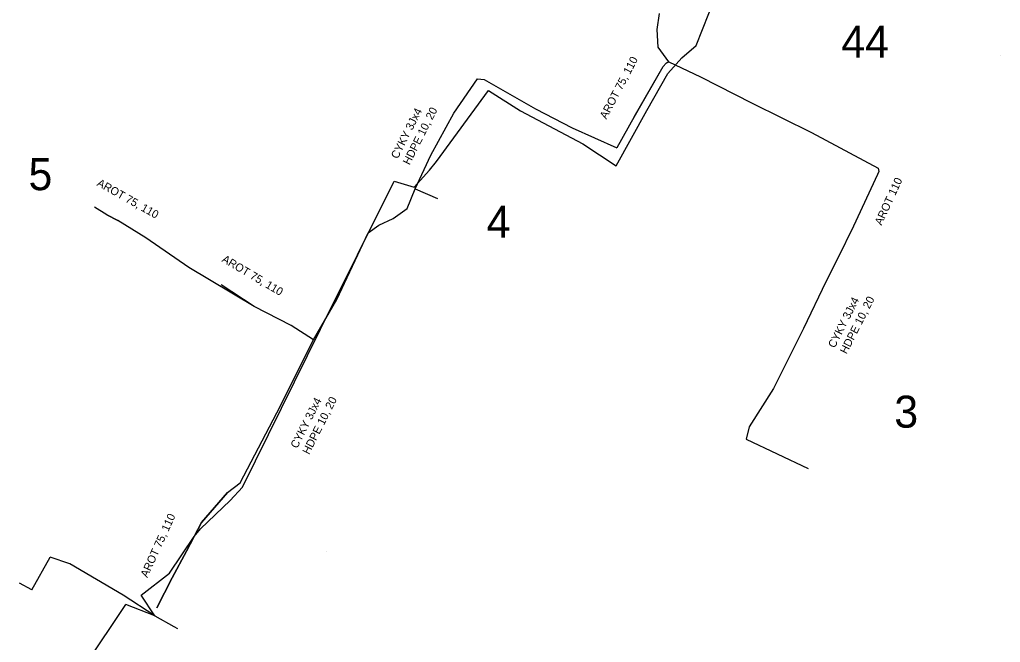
# Model space of a CAD drawing. Extents: x -651943 to -618711, y -1138561 to -1100552.
# Drawn here: x -642518.9 to -642427, y -1114396.7 to -1114338.4 of the extents above; entities that cross this region are included whole.
import ezdxf

# ---------------------------------------------------------------- set-up
doc = ezdxf.new("R2010")
doc.units = 0
for name, color, linetype in [('KT optika', 7, 'Continuous'), ('KT trasa', 7, 'Continuous'), ('KT zařízení', 7, 'Continuous'), ('SATT bloky', 7, 'Continuous'), ('SATT stanice', 7, 'Continuous')]:
    doc.layers.add(name, color=color, linetype=linetype)

# ---------------------------------------------------------------- blocks, each defined once
blk = doc.blocks.new('POINT_DISPLAY')
blk.add_line((0, 0), (0, 0))

msp = doc.modelspace()

# ---------------------------------------------------------------- linework, layer by layer
at = {"layer": 'KT optika'}
for p, q in [((-642459.15, -1114339.29), (-642458.96, -1114337.79)), ((-642459.08, -1114340.92), (-642459.15, -1114339.29)), ((-642458.07, -1114342.31), (-642459.08, -1114340.92)), ((-642461.31, -1114347.46), (-642458.59, -1114342.76)), ((-642458.31, -1114342.44), (-642458.59, -1114342.76)), ((-642458.07, -1114342.31), (-642458.31, -1114342.44)), ((-642458.07, -1114342.31), (-642455.1, -1114343.7)), ((-642455.1, -1114343.7), (-642450.26, -1114346.17)), ((-642478.23, -1114347.12), (-642476.01, -1114343.9)), ((-642476.01, -1114343.9), (-642475.37, -1114343.95)), ((-642475.37, -1114343.95), (-642470.55, -1114346.71)), ((-642450.26, -1114346.17), (-642444.69, -1114348.92)), ((-642480.38, -1114351.06), (-642478.23, -1114347.12)), ((-642470.55, -1114346.71), (-642467.12, -1114348.48)), ((-642461.31, -1114347.46), (-642462.95, -1114350.38)), ((-642467.12, -1114348.48), (-642462.95, -1114350.38)), ((-642444.69, -1114348.92), (-642438.45, -1114352.26)), ((-642481.85, -1114354.22), (-642480.38, -1114351.06)), ((-642438.51, -1114352.85), (-642440.75, -1114357.71)), ((-642438.4, -1114352.57), (-642438.51, -1114352.85)), ((-642438.45, -1114352.26), (-642438.4, -1114352.57)), ((-642482.59, -1114356.04), (-642481.85, -1114354.22)), ((-642481.85, -1114354.22), (-642479.75, -1114355.1)), ((-642510.73, -1114356.65), (-642511.9, -1114355.94)), ((-642510.73, -1114356.65), (-642509.7, -1114357.18)), ((-642483.9, -1114356.99), (-642482.59, -1114356.04)), ((-642507.08, -1114358.81), (-642509.7, -1114357.18)), ((-642486.23, -1114358.32), (-642485.24, -1114357.62)), ((-642485.24, -1114357.62), (-642483.9, -1114356.99)), ((-642489.19, -1114364.58), (-642486.23, -1114358.32)), ((-642440.75, -1114357.71), (-642442.24, -1114360.7)), ((-642503.05, -1114361.57), (-642507.08, -1114358.81)), ((-642442.24, -1114360.7), (-642443.36, -1114362.92)), ((-642496.94, -1114365.23), (-642503.05, -1114361.57)), ((-642443.36, -1114362.92), (-642445.45, -1114367.28)), ((-642491.36, -1114368.35), (-642489.19, -1114364.58)), ((-642493.46, -1114367.02), (-642496.94, -1114365.23)), ((-642491.36, -1114368.35), (-642493.46, -1114367.02)), ((-642445.45, -1114367.28), (-642448.27, -1114372.9)), ((-642494.47, -1114374.51), (-642491.36, -1114368.35)), ((-642448.27, -1114372.9), (-642450.54, -1114376.49)), ((-642498.25, -1114381.76), (-642494.47, -1114374.53)), ((-642494.47, -1114374.53), (-642494.47, -1114374.51)), ((-642450.54, -1114376.49), (-642450.81, -1114377.65)), ((-642450.81, -1114377.65), (-642445.02, -1114380.412)), ((-642499.42, -1114382.67), (-642498.25, -1114381.76)), ((-642499.42, -1114382.67), (-642501.85, -1114385.47)), ((-642501.85, -1114385.47), (-642503.27, -1114388.15)), ((-642503.27, -1114388.15), (-642504.61, -1114390.65)), ((-642504.61, -1114390.65), (-642506.04, -1114393.47))]:
    msp.add_line(p, q, dxfattribs=at)
at = {"layer": 'KT trasa'}
for p, q in [((-642455.513, -1114340.77), (-642453.452, -1114335.606)), ((-642459.15, -1114339.29), (-642458.96, -1114337.79)), ((-642459.08, -1114340.92), (-642459.15, -1114339.29)), ((-642458.07, -1114342.31), (-642459.08, -1114340.92)), ((-642456.853, -1114341.95), (-642455.513, -1114340.77)), ((-642458.173, -1114343.39), (-642456.853, -1114341.95)), ((-642461.31, -1114347.46), (-642458.59, -1114342.76)), ((-642458.31, -1114342.44), (-642458.59, -1114342.76)), ((-642458.07, -1114342.31), (-642458.31, -1114342.44)), ((-642458.07, -1114342.31), (-642455.1, -1114343.7)), ((-642460.133, -1114346.86), (-642458.173, -1114343.39)), ((-642455.1, -1114343.7), (-642450.26, -1114346.17)), ((-642478.23, -1114347.12), (-642476.01, -1114343.9)), ((-642476.01, -1114343.9), (-642475.37, -1114343.95)), ((-642475.37, -1114343.95), (-642470.55, -1114346.71)), ((-642479.853, -1114351.66), (-642474.973, -1114345.01)), ((-642474.973, -1114345.01), (-642471.963, -1114346.9)), ((-642450.26, -1114346.17), (-642444.69, -1114348.92)), ((-642480.38, -1114351.06), (-642478.23, -1114347.12)), ((-642471.963, -1114346.9), (-642466.133, -1114349.98)), ((-642470.55, -1114346.71), (-642467.12, -1114348.48)), ((-642463.003, -1114352.06), (-642460.133, -1114346.86)), ((-642461.31, -1114347.46), (-642462.95, -1114350.38)), ((-642467.12, -1114348.48), (-642462.95, -1114350.38)), ((-642444.69, -1114348.92), (-642438.45, -1114352.26)), ((-642466.133, -1114349.98), (-642463.003, -1114352.06)), ((-642481.85, -1114354.22), (-642480.38, -1114351.06)), ((-642480.513, -1114352.45), (-642479.853, -1114351.66)), ((-642481.923, -1114354.06), (-642480.513, -1114352.45)), ((-642438.51, -1114352.85), (-642440.75, -1114357.71)), ((-642438.4, -1114352.57), (-642438.51, -1114352.85)), ((-642438.45, -1114352.26), (-642438.4, -1114352.57)), ((-642490.713, -1114367.34), (-642483.803, -1114353.49)), ((-642483.803, -1114353.49), (-642481.923, -1114354.06)), ((-642482.59, -1114356.04), (-642481.85, -1114354.22)), ((-642481.85, -1114354.22), (-642479.75, -1114355.1)), ((-642510.73, -1114356.65), (-642511.9, -1114355.94)), ((-642510.73, -1114356.65), (-642509.7, -1114357.18)), ((-642483.9, -1114356.99), (-642482.59, -1114356.04)), ((-642507.08, -1114358.81), (-642509.7, -1114357.18)), ((-642486.23, -1114358.32), (-642485.24, -1114357.62)), ((-642485.24, -1114357.62), (-642483.9, -1114356.99)), ((-642489.19, -1114364.58), (-642486.23, -1114358.32)), ((-642440.75, -1114357.71), (-642442.24, -1114360.7)), ((-642503.05, -1114361.57), (-642507.08, -1114358.81)), ((-642442.24, -1114360.7), (-642443.36, -1114362.92)), ((-642496.94, -1114365.23), (-642503.05, -1114361.57)), ((-642443.36, -1114362.92), (-642445.45, -1114367.28)), ((-642491.36, -1114368.35), (-642489.19, -1114364.58)), ((-642493.46, -1114367.02), (-642496.94, -1114365.23)), ((-642498.033, -1114382.16), (-642490.713, -1114367.34)), ((-642491.36, -1114368.35), (-642493.46, -1114367.02)), ((-642445.45, -1114367.28), (-642448.27, -1114372.9)), ((-642494.47, -1114374.51), (-642491.36, -1114368.35)), ((-642448.27, -1114372.9), (-642450.54, -1114376.49)), ((-642498.25, -1114381.76), (-642494.47, -1114374.53)), ((-642494.47, -1114374.53), (-642494.47, -1114374.51)), ((-642450.54, -1114376.49), (-642450.81, -1114377.65)), ((-642450.81, -1114377.65), (-642445.02, -1114380.412)), ((-642499.42, -1114382.67), (-642498.25, -1114381.76)), ((-642499.192, -1114383.416), (-642498.033, -1114382.16)), ((-642499.42, -1114382.67), (-642501.85, -1114385.47)), ((-642501.972, -1114386.062), (-642499.192, -1114383.416)), ((-642501.85, -1114385.47), (-642503.27, -1114388.15)), ((-642502.553, -1114386.77), (-642501.972, -1114386.062)), ((-642504.853, -1114390.22), (-642502.553, -1114386.77)), ((-642517.77, -1114391.769), (-642516.033, -1114388.72)), ((-642514.199, -1114389.345), (-642516.033, -1114388.72)), ((-642503.27, -1114388.15), (-642504.61, -1114390.65)), ((-642509.208, -1114392.279), (-642514.199, -1114389.345)), ((-642507.503, -1114392.26), (-642504.853, -1114390.22)), ((-642504.61, -1114390.65), (-642506.04, -1114393.47)), ((-642517.77, -1114391.769), (-642518.908, -1114391.14)), ((-642506.223, -1114394.2), (-642509.208, -1114392.279)), ((-642506.223, -1114394.2), (-642507.503, -1114392.26)), ((-642513.183, -1114399.46), (-642508.958, -1114393.157)), ((-642506.223, -1114394.2), (-642508.958, -1114393.157)), ((-642506.223, -1114394.2), (-642504.443, -1114395.21)), ((-642504.443, -1114395.21), (-642504.109, -1114395.396))]:
    msp.add_line(p, q, dxfattribs=at)
at = {"layer": 'KT zařízení'}
for p, q in [((-642461.33, -1114347.5), (-642458.59, -1114342.76)), ((-642458.59, -1114342.76), (-642458.31, -1114342.44)), ((-642458.31, -1114342.44), (-642458.07, -1114342.31)), ((-642438.51, -1114352.85), (-642440.75, -1114357.71)), ((-642509.7, -1114357.18), (-642510.73, -1114356.65)), ((-642496.94, -1114365.23), (-642500.03, -1114363.21)), ((-642501.85, -1114385.47), (-642499.42, -1114382.67)), ((-642503.27, -1114388.15), (-642501.85, -1114385.47)), ((-642504.61, -1114390.65), (-642503.27, -1114388.15)), ((-642506.04, -1114393.47), (-642504.61, -1114390.65))]:
    msp.add_line(p, q, dxfattribs=at)

# ---------------------------------------------------------------- block references
at = {"layer": 'SATT stanice'}
for p in [(-642427.001, -1114341.702), (-642490.105, -1114388.18)]:
    msp.add_blockref('POINT_DISPLAY', p, dxfattribs=at)

# ---------------------------------------------------------------- texts
at = {"layer": 'KT zařízení'}
for s, height, rotation, p in [('AROT 75, 110 ', 0.74996, 62.22648, (-642463.926, -1114347.739)), ('HDPE 10, 20', 0.74998, 63.12851, (-642482.374, -1114352.027)), ('CYKY 3Jx4', 0.75, 63.12851, (-642483.486, -1114351.463)), ('AROT 75, 110 ', 0.74997, 330.5344, (-642511.729, -1114353.873)), ('AROT 110', 0.75, 65.25477, (-642438.143, -1114357.677)), ('AROT 75, 110 ', 0.74997, 329.42226, (-642500.022, -1114360.996)), ('CYKY 3Jx4', 0.75, 63.12851, (-642442.526, -1114369.178)), ('HDPE 10, 20', 0.74998, 63.12851, (-642441.414, -1114369.742)), ('CYKY 3Jx4', 0.75, 63.12851, (-642492.898, -1114378.588)), ('HDPE 10, 20', 0.74998, 63.12851, (-642491.786, -1114379.152)), ('AROT 75, 110 ', 0.74996, 65.53179, (-642506.937, -1114390.681))]:
    msp.add_text(s, height=height, rotation=rotation, dxfattribs=at).set_placement(p)
at = {"layer": 'SATT bloky'}
for s, p in [('44', (-642441.904, -1114341.919)), ('5', (-642518.074, -1114354.333)), ('4', (-642475.144, -1114358.796)), ('3', (-642436.941, -1114376.583))]:
    msp.add_text(s, height=3, dxfattribs=at).set_placement(p)

doc.saveas('drawing.dxf')
